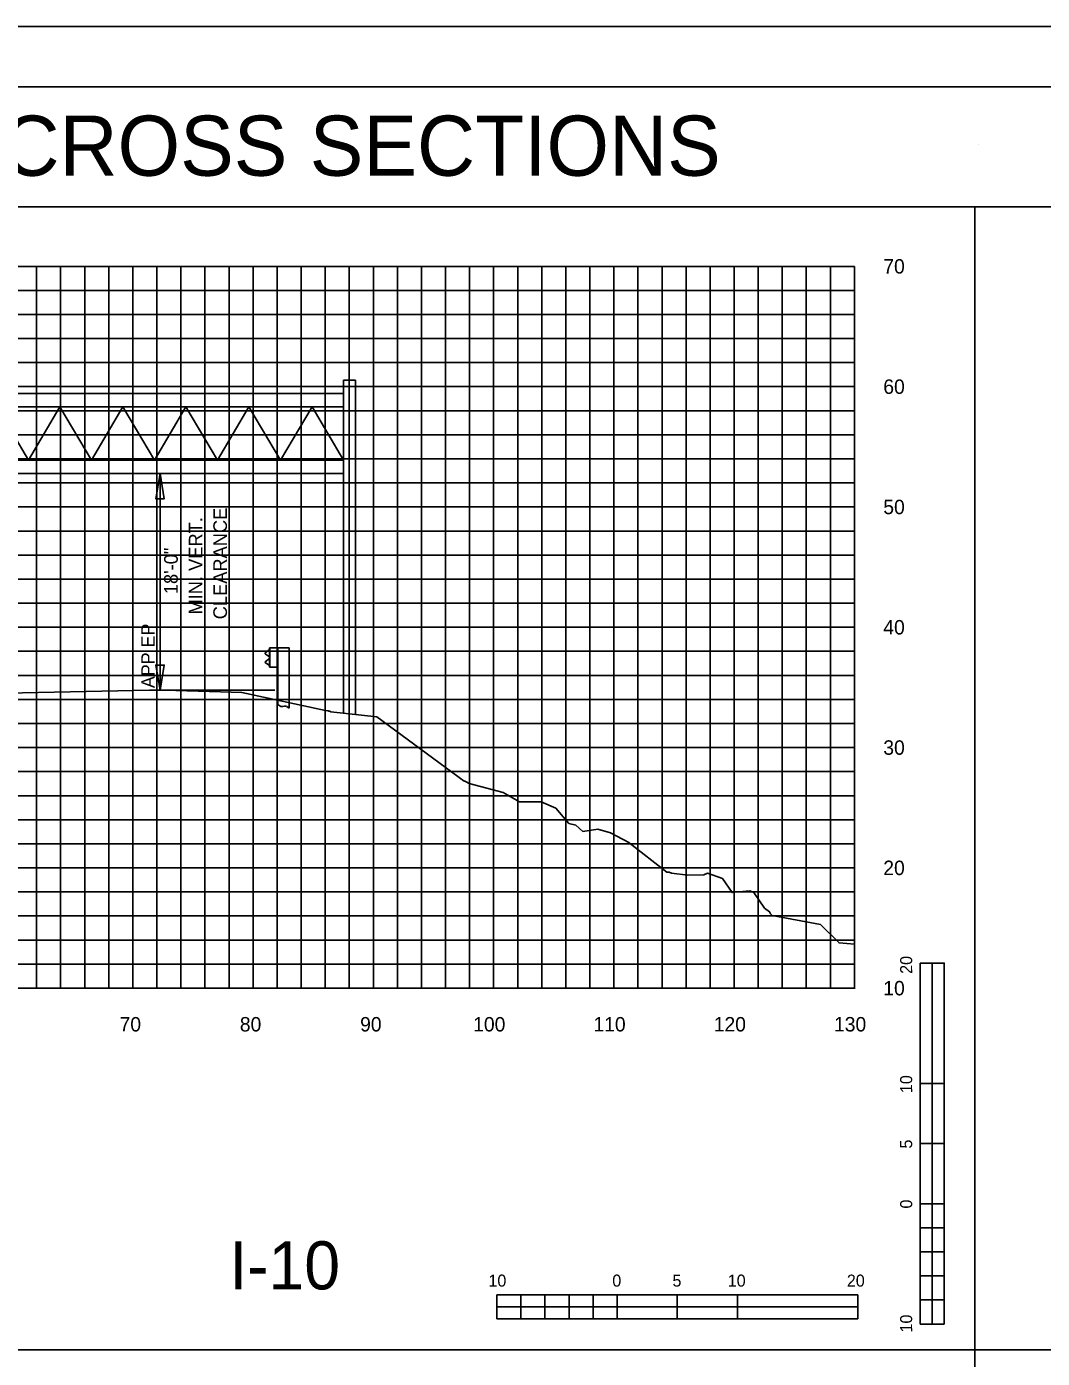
# Model space of a CAD drawing. Extents: x 2193008 to 2198143, y 1236112 to 1237864.
# Drawn here: x 2194608.9 to 2194693.3, y 1237227.3 to 1237338 of the extents above; entities that cross this region are included whole.
import ezdxf

# ---------------------------------------------------------------- set-up
doc = ezdxf.new("R2010")
doc.units = 0
for name, color, linetype in [('3', 7, 'Continuous'), ('31', 7, 'Continuous'), ('60', 7, 'Continuous'), ('ANNO-SHT', 7, 'Continuous'), ('DRAINAGE', 7, 'Continuous'), ('GSDIMS', 7, 'Continuous'), ('Level 1', 7, 'Continuous'), ('Level 33', 7, 'Continuous'), ('Level 55', 7, 'Continuous'), ('LIMT-CSLINE', 7, 'Continuous'), ('M-ROADS', 7, 'Continuous'), ('SHT-BNDRY', 7, 'Continuous')]:
    doc.layers.add(name, color=color, linetype=linetype)

# ---------------------------------------------------------------- blocks, each defined once
blk = doc.blocks.new('SC47208')
at = {"layer": 'Level 1'}
blk.add_line((0, 0), (0, 0), dxfattribs=at)

msp = doc.modelspace()

# ---------------------------------------------------------------- linework, layer by layer
msp.add_lwpolyline([(2194537.69, 1237133.05), (2194837.69, 1237133.05), (2194837.69, 1237323.05), (2194537.69, 1237323.05)], close=True)
at = {"layer": '3'}
for p, q in [((2194687.69, 1237228.05), (2194687.69, 1237323.05)), ((2194635.2, 1237280.97), (2194635.2, 1237308.65)), ((2194636.2, 1237308.65), (2194635.2, 1237308.65)), ((2194636.2, 1237280.86), (2194636.2, 1237308.65)), ((2194619.96, 1237282.88), (2194619.96, 1237300.88)), ((2194619.96, 1237282.88), (2194619.96, 1237294.29)), ((2194687.69, 1237133.05), (2194687.69, 1237228.05))]:
    msp.add_line(p, q, dxfattribs=at)
at = {"layer": '60'}
for p, q in [((2194677.69, 1237258.11), (2194677.69, 1237318.11)), ((2194677.75, 1237298.11), (2194677.69, 1237298.11)), ((2194677.75, 1237288.11), (2194677.69, 1237288.11)), ((2194677.75, 1237278.11), (2194677.69, 1237278.11)), ((2194677.75, 1237268.11), (2194677.69, 1237268.11)), ((2194547.69, 1237258.11), (2194677.69, 1237258.11)), ((2194617.69, 1237258.05), (2194617.69, 1237258.11)), ((2194627.69, 1237258.05), (2194627.69, 1237258.11)), ((2194637.69, 1237258.05), (2194637.69, 1237258.11)), ((2194647.69, 1237258.05), (2194647.69, 1237258.11)), ((2194657.69, 1237258.05), (2194657.69, 1237258.11)), ((2194667.69, 1237258.05), (2194667.69, 1237258.11)), ((2194677.69, 1237258.05), (2194677.69, 1237258.11)), ((2194677.75, 1237258.11), (2194677.69, 1237258.11))]:
    msp.add_line(p, q, dxfattribs=at)
at = {"layer": 'GSDIMS'}
for p, q in [((2194591.93, 1237307.54), (2194635.2, 1237307.54)), ((2194591.93, 1237306.43), (2194635.2, 1237306.43)), ((2194606.39, 1237306.43), (2194609.01, 1237301.99)), ((2194611.63, 1237306.43), (2194609.01, 1237301.99)), ((2194611.63, 1237306.43), (2194614.25, 1237301.99)), ((2194616.87, 1237306.43), (2194614.25, 1237301.99)), ((2194616.87, 1237306.43), (2194619.49, 1237301.99)), ((2194622.11, 1237306.43), (2194619.49, 1237301.99)), ((2194622.11, 1237306.43), (2194624.73, 1237301.99)), ((2194627.35, 1237306.43), (2194624.73, 1237301.99)), ((2194627.35, 1237306.43), (2194629.97, 1237301.99)), ((2194632.59, 1237306.43), (2194629.97, 1237301.99)), ((2194632.59, 1237306.43), (2194635.2, 1237301.99)), ((2194591.93, 1237301.99), (2194635.2, 1237301.99)), ((2194591.93, 1237300.88), (2194635.2, 1237300.88)), ((2194629.5, 1237282.88), (2194619.96, 1237282.88))]:
    msp.add_line(p, q, dxfattribs=at)
for points in [[(2194619.96, 1237300.88), (2194620.31, 1237298.79), (2194619.6, 1237298.79)], [(2194619.96, 1237282.88), (2194619.6, 1237284.96), (2194620.31, 1237284.96)]]:
    msp.add_lwpolyline(points, close=True, dxfattribs=at)
at = {"layer": 'Level 1'}
for p, q in [((2194629.05, 1237286.25), (2194628.7, 1237285.97)), ((2194628.7, 1237285.91), (2194629.05, 1237285.65)), ((2194629.05, 1237285.52), (2194628.7, 1237285.24)), ((2194629.05, 1237286.39), (2194629.05, 1237284.78)), ((2194630.69, 1237286.39), (2194629.05, 1237286.39)), ((2194629.09, 1237286.39), (2194629.09, 1237284.78)), ((2194629.7, 1237286.39), (2194629.7, 1237284.78)), ((2194629.75, 1237286.39), (2194629.75, 1237281.69)), ((2194630.69, 1237286.39), (2194630.69, 1237281.39)), ((2194628.7, 1237285.18), (2194629.05, 1237284.92)), ((2194629.75, 1237284.78), (2194629.05, 1237284.78)), ((2194629.75, 1237281.69), (2194629.91, 1237281.58)), ((2194629.91, 1237281.58), (2194630, 1237281.53)), ((2194630.15, 1237281.51), (2194630.32, 1237281.56)), ((2194630.49, 1237281.53), (2194630.69, 1237281.39)), ((2194683.16, 1237260.19), (2194683.16, 1237230.19)), ((2194685.16, 1237260.19), (2194683.16, 1237260.19)), ((2194685.16, 1237260.19), (2194685.16, 1237250.19)), ((2194685.16, 1237260.19), (2194685.16, 1237230.19)), ((2194684.16, 1237250.19), (2194683.16, 1237250.19)), ((2194685.16, 1237250.19), (2194683.16, 1237250.19)), ((2194684.16, 1237250.19), (2194684.16, 1237245.19)), ((2194685.16, 1237245.19), (2194683.16, 1237245.19)), ((2194685.16, 1237245.19), (2194684.16, 1237245.19)), ((2194685.16, 1237245.19), (2194685.16, 1237240.19)), ((2194684.16, 1237240.19), (2194683.16, 1237240.19)), ((2194685.16, 1237240.19), (2194683.16, 1237240.19)), ((2194684.16, 1237240.19), (2194684.16, 1237238.19)), ((2194685.16, 1237238.19), (2194684.16, 1237238.19)), ((2194685.16, 1237238.19), (2194685.16, 1237236.19)), ((2194684.16, 1237236.19), (2194683.16, 1237236.19)), ((2194684.16, 1237236.19), (2194684.16, 1237234.19)), ((2194685.16, 1237234.19), (2194684.16, 1237234.19)), ((2194685.16, 1237234.19), (2194685.16, 1237232.19)), ((2194677.96, 1237232.63), (2194647.96, 1237232.63)), ((2194647.96, 1237230.63), (2194647.96, 1237232.63)), ((2194649.96, 1237231.63), (2194649.96, 1237232.63)), ((2194653.96, 1237231.63), (2194653.96, 1237232.63)), ((2194657.96, 1237231.63), (2194657.96, 1237232.63)), ((2194657.96, 1237230.63), (2194657.96, 1237232.63)), ((2194662.96, 1237230.63), (2194662.96, 1237232.63)), ((2194667.96, 1237231.63), (2194667.96, 1237232.63)), ((2194667.96, 1237230.63), (2194667.96, 1237232.63)), ((2194677.96, 1237230.63), (2194677.96, 1237232.63)), ((2194649.96, 1237231.63), (2194647.96, 1237231.63)), ((2194651.96, 1237230.63), (2194651.96, 1237231.63)), ((2194653.96, 1237231.63), (2194651.96, 1237231.63)), ((2194655.96, 1237230.63), (2194655.96, 1237231.63)), ((2194657.96, 1237231.63), (2194655.96, 1237231.63)), ((2194662.96, 1237230.63), (2194662.96, 1237231.63)), ((2194667.96, 1237231.63), (2194662.96, 1237231.63)), ((2194684.16, 1237232.19), (2194683.16, 1237232.19)), ((2194684.16, 1237232.19), (2194684.16, 1237230.19)), ((2194677.96, 1237230.63), (2194647.96, 1237230.63)), ((2194651.96, 1237230.63), (2194649.96, 1237230.63)), ((2194655.96, 1237230.63), (2194653.96, 1237230.63)), ((2194662.96, 1237230.63), (2194657.96, 1237230.63)), ((2194677.96, 1237230.63), (2194667.96, 1237230.63)), ((2194685.16, 1237230.19), (2194683.16, 1237230.19)), ((2194537.69, 1237228.05), (2194837.69, 1237228.05))]:
    msp.add_line(p, q, dxfattribs=at)
for points in [[(2194684.16, 1237250.19), (2194684.16, 1237260.19), (2194685.16, 1237260.19), (2194685.16, 1237250.19)], [(2194683.16, 1237245.19), (2194683.16, 1237250.19), (2194684.16, 1237250.19), (2194684.16, 1237245.19)], [(2194684.16, 1237240.19), (2194684.16, 1237245.19), (2194685.16, 1237245.19), (2194685.16, 1237240.19)], [(2194683.16, 1237238.19), (2194683.16, 1237240.19), (2194684.16, 1237240.19), (2194684.16, 1237238.19)], [(2194684.16, 1237236.19), (2194684.16, 1237238.19), (2194685.16, 1237238.19), (2194685.16, 1237236.19)], [(2194683.16, 1237234.19), (2194683.16, 1237236.19), (2194684.16, 1237236.19), (2194684.16, 1237234.19)], [(2194684.16, 1237232.19), (2194684.16, 1237234.19), (2194685.16, 1237234.19), (2194685.16, 1237232.19)], [(2194647.96, 1237232.63), (2194649.96, 1237232.63), (2194649.96, 1237231.63), (2194647.96, 1237231.63)], [(2194651.96, 1237232.63), (2194653.96, 1237232.63), (2194653.96, 1237231.63), (2194651.96, 1237231.63)], [(2194655.96, 1237232.63), (2194657.96, 1237232.63), (2194657.96, 1237231.63), (2194655.96, 1237231.63)], [(2194662.96, 1237232.63), (2194667.96, 1237232.63), (2194667.96, 1237231.63), (2194662.96, 1237231.63)], [(2194649.96, 1237231.63), (2194651.96, 1237231.63), (2194651.96, 1237230.63), (2194649.96, 1237230.63)], [(2194653.96, 1237231.63), (2194655.96, 1237231.63), (2194655.96, 1237230.63), (2194653.96, 1237230.63)], [(2194657.96, 1237231.63), (2194662.96, 1237231.63), (2194662.96, 1237230.63), (2194657.96, 1237230.63)], [(2194667.96, 1237231.63), (2194677.96, 1237231.63), (2194677.96, 1237230.63), (2194667.96, 1237230.63)], [(2194683.16, 1237230.19), (2194683.16, 1237232.19), (2194684.16, 1237232.19), (2194684.16, 1237230.19)]]:
    msp.add_lwpolyline(points, close=True, dxfattribs=at)
for centre, major_axis, start_param, end_param in [((2194628.74, 1237285.94), (-0.0469, 0), 5.497787, 7.096872), ((2194628.74, 1237285.21), (-0.0469, 0), 5.497787, 7.096872), ((2194630.1, 1237281.7), (-0.196, 0), 1.064721, 1.848328), ((2194630.37, 1237281.37), (-0.196, 0), 4.106844, 4.989921)]:
    msp.add_ellipse(centre, major_axis=major_axis, ratio=0.978687, start_param=start_param, end_param=end_param, dxfattribs=at)
at = {"layer": 'M-ROADS'}
for p, q in [((2194547.69, 1237318.11), (2194677.69, 1237318.11)), ((2194609.69, 1237258.11), (2194609.69, 1237318.11)), ((2194611.69, 1237258.11), (2194611.69, 1237318.11)), ((2194613.69, 1237258.11), (2194613.69, 1237318.11)), ((2194615.69, 1237258.11), (2194615.69, 1237318.11)), ((2194617.69, 1237258.11), (2194617.69, 1237318.11)), ((2194619.69, 1237258.11), (2194619.69, 1237318.11)), ((2194621.69, 1237258.11), (2194621.69, 1237318.11)), ((2194623.69, 1237258.11), (2194623.69, 1237318.11)), ((2194625.69, 1237258.11), (2194625.69, 1237318.11)), ((2194627.69, 1237258.11), (2194627.69, 1237318.11)), ((2194629.69, 1237258.11), (2194629.69, 1237318.11)), ((2194631.69, 1237258.11), (2194631.69, 1237318.11)), ((2194633.69, 1237258.11), (2194633.69, 1237318.11)), ((2194635.69, 1237258.11), (2194635.69, 1237318.11)), ((2194637.69, 1237258.11), (2194637.69, 1237318.11)), ((2194639.69, 1237258.11), (2194639.69, 1237318.11)), ((2194641.69, 1237258.11), (2194641.69, 1237318.11)), ((2194643.69, 1237258.11), (2194643.69, 1237318.11)), ((2194645.69, 1237258.11), (2194645.69, 1237318.11)), ((2194647.69, 1237258.11), (2194647.69, 1237318.11)), ((2194649.69, 1237258.11), (2194649.69, 1237318.11)), ((2194651.69, 1237258.11), (2194651.69, 1237318.11)), ((2194653.69, 1237258.11), (2194653.69, 1237318.11)), ((2194655.69, 1237258.11), (2194655.69, 1237318.11)), ((2194657.69, 1237258.11), (2194657.69, 1237318.11)), ((2194659.69, 1237258.11), (2194659.69, 1237318.11)), ((2194661.69, 1237258.11), (2194661.69, 1237318.11)), ((2194663.69, 1237258.11), (2194663.69, 1237318.11)), ((2194665.69, 1237258.11), (2194665.69, 1237318.11)), ((2194667.69, 1237258.11), (2194667.69, 1237318.11)), ((2194669.69, 1237258.11), (2194669.69, 1237318.11)), ((2194671.69, 1237258.11), (2194671.69, 1237318.11)), ((2194673.69, 1237258.11), (2194673.69, 1237318.11)), ((2194675.69, 1237258.11), (2194675.69, 1237318.11)), ((2194677.69, 1237258.11), (2194677.69, 1237318.11)), ((2194547.69, 1237316.11), (2194677.69, 1237316.11)), ((2194547.69, 1237314.11), (2194677.69, 1237314.11)), ((2194547.69, 1237312.11), (2194677.69, 1237312.11)), ((2194547.69, 1237310.11), (2194677.69, 1237310.11)), ((2194547.69, 1237308.11), (2194677.69, 1237308.11)), ((2194547.69, 1237306.11), (2194677.69, 1237306.11)), ((2194547.69, 1237304.11), (2194677.69, 1237304.11)), ((2194547.69, 1237302.11), (2194677.69, 1237302.11)), ((2194547.69, 1237300.11), (2194677.69, 1237300.11)), ((2194547.69, 1237298.11), (2194677.69, 1237298.11)), ((2194547.69, 1237296.11), (2194677.69, 1237296.11)), ((2194547.69, 1237294.11), (2194677.69, 1237294.11)), ((2194547.69, 1237292.11), (2194677.69, 1237292.11)), ((2194547.69, 1237290.11), (2194677.69, 1237290.11)), ((2194547.69, 1237288.11), (2194677.69, 1237288.11)), ((2194547.69, 1237286.11), (2194677.69, 1237286.11)), ((2194547.69, 1237284.11), (2194677.69, 1237284.11)), ((2194547.69, 1237282.11), (2194677.69, 1237282.11)), ((2194547.69, 1237280.11), (2194677.69, 1237280.11)), ((2194547.69, 1237278.11), (2194677.69, 1237278.11)), ((2194547.69, 1237276.11), (2194677.69, 1237276.11)), ((2194547.69, 1237274.11), (2194677.69, 1237274.11)), ((2194547.69, 1237272.11), (2194677.69, 1237272.11)), ((2194547.69, 1237270.11), (2194677.69, 1237270.11)), ((2194547.69, 1237268.11), (2194677.69, 1237268.11)), ((2194547.69, 1237266.11), (2194677.69, 1237266.11)), ((2194547.69, 1237264.11), (2194677.69, 1237264.11)), ((2194547.69, 1237262.11), (2194677.69, 1237262.11)), ((2194547.69, 1237260.11), (2194677.69, 1237260.11)), ((2194547.69, 1237258.11), (2194677.69, 1237258.11))]:
    msp.add_line(p, q, dxfattribs=at)
msp.add_lwpolyline([(2194512.69, 1237118.04), (2194852.69, 1237118.04), (2194852.69, 1237338.04), (2194512.69, 1237338.04)], close=True, dxfattribs=at)
msp.add_lwpolyline([(2194607.2, 1237282.62), (2194612.47, 1237282.74), (2194619.07, 1237282.88), (2194619.96, 1237282.88), (2194620.32, 1237282.88), (2194624.97, 1237282.73), (2194626.75, 1237282.68), (2194633.7, 1237281.2), (2194633.92, 1237281.15), (2194633.98, 1237281.14), (2194634.07, 1237281.13), (2194634.15, 1237281.08), (2194637.99, 1237280.67), (2194645.24, 1237275.32), (2194645.29, 1237275.32), (2194645.4, 1237275.26), (2194645.65, 1237275.13), (2194648.47, 1237274.38), (2194649.83, 1237273.61), (2194651.63, 1237273.61), (2194652.85, 1237273.06), (2194653.95, 1237271.79), (2194654.52, 1237271.66), (2194655.1, 1237271.14), (2194656.36, 1237271.33), (2194657.42, 1237271.01), (2194658.94, 1237270.23), (2194658.96, 1237270.2), (2194662.09, 1237267.74), (2194662.28, 1237267.74), (2194662.48, 1237267.68), (2194663.85, 1237267.51), (2194665.18, 1237267.52), (2194665.48, 1237267.66), (2194666.72, 1237267.22), (2194667.51, 1237266.06), (2194667.57, 1237266.08), (2194668.11, 1237266.11), (2194669, 1237266.21), (2194669.33, 1237266.07), (2194670.2, 1237264.76), (2194670.63, 1237264.46), (2194670.7, 1237264.28), (2194670.85, 1237264.16), (2194674.87, 1237263.39), (2194676.42, 1237261.87), (2194677.69, 1237261.78)], dxfattribs=at)
at = {"layer": 'SHT-BNDRY'}
msp.add_lwpolyline([(2194525.19, 1237123.04), (2194847.69, 1237123.04), (2194847.69, 1237333.04), (2194525.19, 1237333.04)], close=True, dxfattribs=at)

# ---------------------------------------------------------------- block references
at = {"layer": 'DRAINAGE', "xscale": 0.20000000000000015, "yscale": 0.20000000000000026, "rotation": -116.41666666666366}
msp.add_blockref('SC47208', (2194688.01, 1237328.23), dxfattribs=at)
msp.add_blockref('SC47208', (2194688.01, 1237328.23), dxfattribs=at)

# ---------------------------------------------------------------- texts
at = {"layer": '31'}
for s, p in [('70', (2194680.09, 1237317.51)), ('60', (2194680.09, 1237307.51)), ('50', (2194680.09, 1237297.51)), ('40', (2194680.09, 1237287.51)), ('30', (2194680.09, 1237277.51)), ('20', (2194680.09, 1237267.51)), ('10', (2194680.09, 1237257.51))]:
    msp.add_text(s, height=1.2, dxfattribs=at).set_placement(p)
at = {"layer": 'ANNO-SHT'}
msp.add_text('              SIGN CROSS SECTIONS               ', height=4.9995, rotation=360, dxfattribs=at).set_placement((2194562.56, 1237325.64))
at = {"layer": 'Level 1'}
for s, height, rotation, p in [('20', 0.999, 90.0572, (2194682.49, 1237259.3)), ('10', 0.999, 90.0572, (2194682.49, 1237249.39)), ('5', 1, 90.0572, (2194682.49, 1237244.78)), ('0', 1, 90.0572, (2194682.49, 1237239.79)), ('10', 0.999, 0.0572, (2194647.26, 1237233.3)), ('0', 1, 0.0572, (2194657.56, 1237233.3)), ('5', 0.999, 0.0572, (2194662.56, 1237233.3)), ('10', 0.999, 0.0572, (2194667.16, 1237233.3)), ('20', 0.999, 0.0572, (2194677.06, 1237233.3)), ('10', 0.999, 90.0572, (2194682.49, 1237229.49))]:
    msp.add_text(s, height=height, rotation=rotation, dxfattribs=at).set_placement(p)
at = {"layer": 'Level 33'}
msp.add_text('I-10', height=3.998, rotation=360, dxfattribs=at).set_placement((2194625.71, 1237233.07))
at = {"layer": 'Level 55'}
for s, height, p in [('CLEARANCE', 1.135, (2194625.52, 1237288.77)), ('MIN. VERT.', 1.135, (2194623.48, 1237289.17)), ('18\'-0"', 1.135, (2194621.43, 1237290.86)), ('APP EP', 1.11, (2194619.51, 1237283.05))]:
    msp.add_text(s, height=height, rotation=90, dxfattribs=at).set_placement(p)
at = {"layer": 'LIMT-CSLINE'}
for s, p in [('70', (2194616.59, 1237254.51)), ('80', (2194626.59, 1237254.51)), ('90', (2194636.59, 1237254.51)), ('100', (2194645.99, 1237254.51)), ('110', (2194655.99, 1237254.51)), ('120', (2194665.99, 1237254.51)), ('130', (2194675.99, 1237254.51))]:
    msp.add_text(s, height=1.2, dxfattribs=at).set_placement(p)

doc.saveas('drawing.dxf')
